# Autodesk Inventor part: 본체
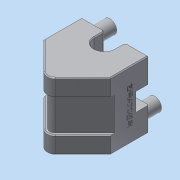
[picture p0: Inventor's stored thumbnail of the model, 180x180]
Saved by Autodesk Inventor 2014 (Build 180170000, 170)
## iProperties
Created: 2025-02
Part Number: 본체
Material: 알루미늄 6061
Document SubType Name: Modeling
Designer: dg
Density: 2.71 g/cm^3
Appearance: 알루미늄 - 평지
Mass: 739.578 g
Surface Area: 337.228 cm^2
Volume: 272.907 cm^3
Author: dg
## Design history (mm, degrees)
sketch "스케치1"
  geometry: L1 (-37, -21)-(0, -58); L2 (0, -58)-(37, -21); L3 (-37, -21)-(-37, 21); L4 (-37, 21)-(37, 21); L5 (37, 21)-(37, -21); 3 further points
  constraints: 10 end point, 2 horizontal alignment, 2 midpoint, 2 vertical alignment, 1 parallel, 1 perpendicular, 1 vertical
  dimensions: "d1" = 90 deg angle of L2 L1; "d2" = 42 distance of L4.end L2.end; "d3" = 74 distance of L3.end L4.end
extrude "돌출1" new body sketch "스케치1" stored distance "d4" = 74; taper "d5" = 0 deg
sketch "스케치2"
  geometry: L1 (37, 21)-(-37, 21) reference; L2 (-37, 21)-(-37, -21) reference; L3 (-11, 9)-(-11, 21); L4 (11, 9)-(11, 21); A1 r 11 centre (0, 9) between (-11, 9) and (11, 9); 1 further point
  constraints: 4 end point, 2 parallel, 2 point on circle, 2 point on line, 2 tangent, 1 centre point, 1 vertical alignment
  dimensions: "d6" = 12 distance from line of A1.centre L1; "d7" = 22 diameter of A1
extrude "돌출2" cut sketch "스케치2" stored distance "d8" = 74; taper "d9" = 0 deg
sketch "스케치3"
  geometry: L1 (48, 74)-(48, 0) reference; L2 (74, 0)-(48, 0) reference; L3 (74, 74)-(74, 0) reference; L4 (48, 74)-(74, 74) reference; C1 r 21 at (37, 37); 1 further point
  constraints: 1 centre point, 1 coincident
  dimensions: "d10" = 42 diameter of C1
extrude "돌출3" cut sketch "스케치3" distance "d11" = 8; taper "d12" = 0 deg
sketch "스케치4"
  geometry: C1 r 16 at (37, 37); A1 r 21 centre (37, 37) between (26, 54.889) and (26, 19.111) reference
  constraints: 1 centre point, 1 coincident
  dimensions: "d13" = 32 diameter of C1
extrude "돌출4" cut sketch "스케치4" distance "d14" = 20; taper "d15" = 0 deg
sketch "스케치5"
  geometry: L1 (16, -7)-(16, 13) reference; L2 (16, 13)-(21, 13) reference; L3 (21, 13)-(21, 21) reference; L4 (21, 21)-(37, 21) reference; L5 (37, 21)-(37, -21) reference; L6 (37, -21)-(0, -58) reference; L7 (0, -58)-(-37, -21) reference; L8 (-37, -21)-(-37, 21) reference; L9 (-37, 21)-(-21, 21) reference; L10 (-21, 21)-(-21, 13) reference; L11 (-21, 13)-(-16, 13) reference; L12 (-16, 13)-(-16, -7) reference; L13 (-16, -7)-(16, -7) reference; L14 (-23, 21)-(-37, 7); L15 (23, 21)-(37, 7); 1 further point
  constraints: 4 end point, 4 point on line, 2 perpendicular
  dimensions: "d16" = 14 distance of L14.start L8.end; "d17" = 14 distance of L4.end L15.start
extrude "돌출5" cut sketch "스케치5" stored distance "d18" = 20; taper "d19" = 0 deg
sketch "스케치6"
  geometry: L1 (19.799, 20)-(19.799, 0) reference; 4 further points
  constraints: 1 horizontal alignment, 1 midpoint, 1 vertical alignment
hole "구멍1" sketch "스케치6" at (9.899, 10) diameter "d20" = 8; stored, may be unused: countersink angle "d24" = 90 deg, drill point angle "d26" = 118 deg; dims "d21" = 6, "d22" = 13, "d23" = 3, "d25" = 8
sketch "스케치7"
  geometry: L1 (0, -58)-(-37, -21) reference; L2 (37, -21)-(0, -58) reference; L3 (34.879, -18.879)-(4.243, -49.515); L4 (-4.243, -49.515)-(-34.879, -18.879); L5 (-37, -21)-(-37, 21) reference; L6 (37, 21)-(37, -21) reference; L7 (-34.879, -18.879)-(-37, -16.757); L8 (34.879, -18.879)-(37, -16.757); A1 r 6 centre (0, -45.272) between (-4.243, -49.515) and (4.243, -49.515); 2 further points
  constraints: 8 end point, 4 point on line, 2 point on circle, 2 tangent, 1 centre point, 1 collinear, 1 horizontal alignment, 1 perpendicular, 1 vertical alignment, 1 other
  dimensions: "d27" = 3 distance between parallel lines of L1 L4; "d28" = 6 radius of A1; "d29" = 30.63604 horizontal distance of L4.start L4.end
extrude "돌출6" cut sketch "스케치7" stored distance "d30" = 36; taper "d31" = 0 deg
fillet "모깎기1" dims "d32" = 9
sketch "스케치8"
  geometry: L1 (14, 47)-(14, 27) reference; L2 (12.251, 12.251)-(37, 37); L3 (37, 37)-(26.927, 37); L4 (37, 37)-(61.749, 61.749); C1 r 7.5 at (12.251, 12.251); C2 r 7.5 at (61.749, 61.749); A1 r 21 centre (37, 37) between (26, 54.889) and (26, 19.111) reference; A2 r 35 centre (37, 37) between (12.251, 12.251) and (61.749, 61.749)
  constraints: 6 end point, 3 centre point, 2 point on circle, 1 coincident, 1 collinear, 1 equal radius, 1 perpendicular
  dimensions: "d33" = 70 diameter of A2; "d34" = 45 deg angle of L3 L2; "d35" = 15 diameter of C1; "d36" = 10.07267 distance of L2.end L3.end
extrude "돌출7" join sketch "스케치8" distance "d37" = 19; taper "d38" = 0 deg
sketch "스케치9"
  geometry: C1 r 7.5 at (0, 0) reference; C2 r 7.5 at (-49.497, -49.497) reference; 3 further points
  constraints: 2 coincident
hole "구멍2" sketch "스케치9" at (0, 0), (-49.497, -49.497) diameter "d39" = 4.917; stored, may be unused: countersink angle "d43" = 90 deg, drill point angle "d45" = 118 deg; dims "d40" = 12, "d41" = 13, "d42" = 3, "d44" = 14
sketch "스케치10"
  geometry: L1 (-4.751, 61)-(-19.751, 61) reference; 2 further points
  constraints: 1 coincident, 1 other
  dimensions: "d46" = 40 distance from line of point (-37, 21) L1
feature "엠보싱1" sketch "스케치10" dims "d47" = 0.5, "d48" = 0
chamfer "모따기1" distance "d49" = 1; stored, may be unused: second distance "d50" = 2, angle "d51" = 45 deg
chamfer "모따기2" distance "d52" = 1; stored, may be unused: second distance "d53" = 2, angle "d54" = 45 deg
chamfer "모따기3" distance "d55" = 1; stored, may be unused: second distance "d56" = 2, angle "d57" = 45 deg
chamfer "모따기5" distance "d61" = 1; stored, may be unused: second distance "d62" = 2, angle "d63" = 45 deg
fillet "모깎기2" dims "d64" = 3
chamfer "모따기6" distance "d65" = 1; stored, may be unused: second distance "d66" = 2, angle "d67" = 45 deg
fillet "모깎기3" dims "d68" = 3
node "솔리드1"
mirror "대칭1"
node "투영된 루프1"
node "투영된 루프2"
node "절단 모서리 투영1"
